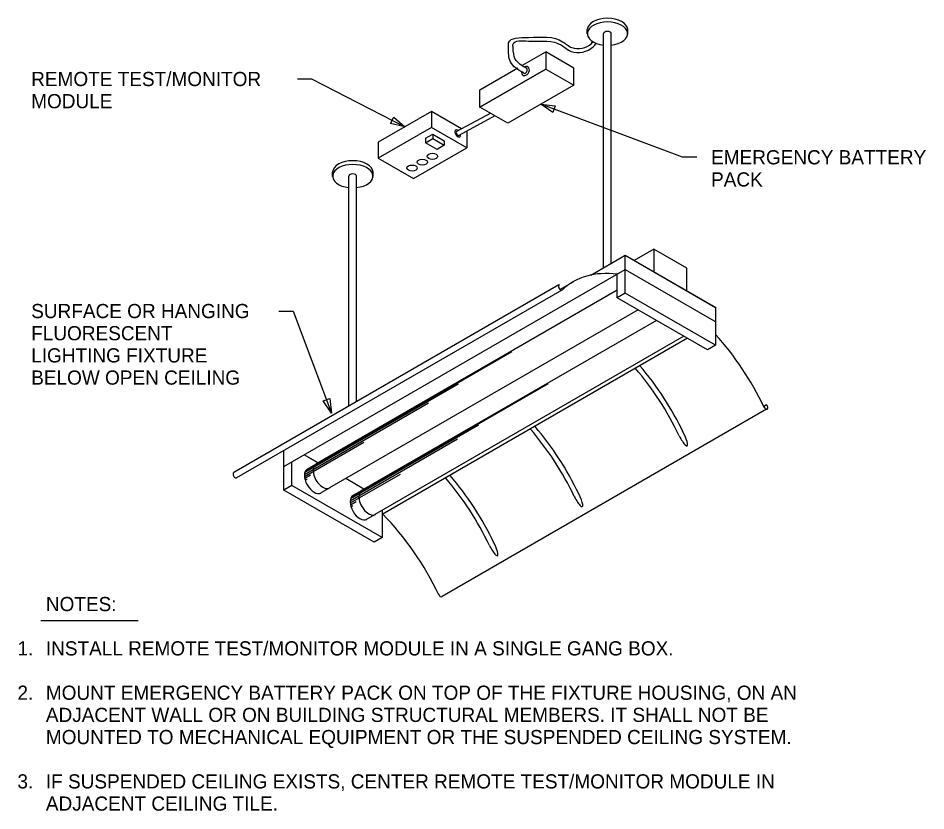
# Model space of a CAD drawing. Extents: x -12092.5 to -12048.3, y -12283.2 to -12205.8.
# Drawn here: x -12091.75 to -12049.13, y -12243.02 to -12205.78 of the extents above; entities that cross this region are included whole.
import ezdxf

# ---------------------------------------------------------------- set-up
doc = ezdxf.new("R2010")
doc.units = 0
for name, color, linetype in [('G-ANNO-TEXT', 7, 'Continuous'), ('G-DETL-LINE', 7, 'Continuous'), ('G-DETL-OTLN', 7, 'Continuous'), ('G-DETL-PATT', 7, 'Continuous')]:
    doc.layers.add(name, color=color, linetype=linetype)

msp = doc.modelspace()

# ---------------------------------------------------------------- linework, layer by layer
at = {"layer": 'G-ANNO-TEXT'}
for p, q in [((-12078.644, -12208.636), (-12077.977, -12208.636)), ((-12077.977, -12208.636), (-12073.601, -12210.884)), ((-12060.552, -12212.314), (-12067.216, -12209.819)), ((-12059.885, -12212.314), (-12060.552, -12212.314)), ((-12079.515, -12219.539), (-12078.848, -12219.539)), ((-12078.848, -12219.539), (-12077.045, -12224.331)), ((-12090.687, -12234.076), (-12086.127, -12234.076))]:
    msp.add_line(p, q, dxfattribs=at)
for points in [[(-12066.65, -12210.209), (-12067.216, -12209.819), (-12066.533, -12209.897)], [(-12074.118, -12210.431), (-12073.601, -12210.884), (-12074.271, -12210.728)], [(-12077.124, -12223.648), (-12077.045, -12224.331), (-12077.436, -12223.765)]]:
    msp.add_lwpolyline(points, close=True, dxfattribs=at)
at = {"layer": 'G-DETL-LINE'}
for p, q in [((-12063.629, -12218.559), (-12077.781, -12226.73)), ((-12062.643, -12219.484), (-12077.131, -12227.849)), ((-12061.786, -12219.978), (-12075.629, -12227.971)), ((-12060.492, -12220.726), (-12075.004, -12229.104))]:
    msp.add_line(p, q, dxfattribs=at)
for centre, major_axis, ratio, start_param, end_param in [((-12065.474, -12226.817), (-4.221, 7.311), 0.57735, 4.575874, 5.027866), ((-12065.263, -12226.695), (-4.221, 7.311), 0.57735, 4.575874, 5.027851), ((-12070.186, -12229.552), (-4.221, 7.311), 0.57735, 4.575874, 5.027851), ((-12070.398, -12229.674), (-4.221, 7.311), 0.57735, 4.575874, 5.027866), ((-12060.612, -12225.337), (0.271, -0.537), 0.202786, 4.723764, 7.865371), ((-12074.38, -12231.977), (-4.221, 7.311), 0.57735, 4.575874, 5.027866), ((-12074.168, -12231.855), (-4.221, 7.311), 0.57735, 4.575874, 5.027851), ((-12065.536, -12228.194), (0.271, -0.537), 0.202786, 4.723764, 7.865371), ((-12069.518, -12230.497), (0.271, -0.537), 0.202786, 4.723764, 7.865371)]:
    msp.add_ellipse(centre, major_axis=major_axis, ratio=ratio, start_param=start_param, end_param=end_param, dxfattribs=at)
at = {"layer": 'G-DETL-OTLN'}
for p, q in [((-12065.034, -12206.522), (-12065.034, -12206.311)), ((-12064.262, -12217.503), (-12064.262, -12206.505)), ((-12063.902, -12217.295), (-12063.902, -12206.505)), ((-12063.132, -12206.524), (-12063.132, -12206.313)), ((-12068.067, -12207.988), (-12066.983, -12207.361)), ((-12065.668, -12208.121), (-12066.983, -12207.361)), ((-12066.983, -12207.361), (-12066.983, -12208.167)), ((-12066.983, -12207.361), (-12066.983, -12208.168)), ((-12070.077, -12209.148), (-12068.294, -12208.119)), ((-12070.077, -12209.955), (-12066.981, -12208.167)), ((-12066.983, -12208.168), (-12070.077, -12209.955)), ((-12066.983, -12208.167), (-12065.668, -12208.926)), ((-12066.981, -12208.167), (-12065.668, -12208.926)), ((-12065.668, -12208.926), (-12065.668, -12208.121)), ((-12070.077, -12209.955), (-12070.077, -12209.148)), ((-12065.668, -12208.926), (-12068.763, -12210.713)), ((-12068.763, -12210.713), (-12070.077, -12209.955)), ((-12072.353, -12210.163), (-12074.85, -12211.605)), ((-12072.353, -12210.163), (-12072.353, -12210.916)), ((-12070.931, -12210.983), (-12072.353, -12210.163)), ((-12069.567, -12210.249), (-12071.166, -12211.11)), ((-12069.364, -12210.371), (-12071.064, -12211.286)), ((-12072.353, -12210.916), (-12074.85, -12212.358)), ((-12070.691, -12211.875), (-12072.353, -12210.916)), ((-12072.626, -12211.42), (-12072.288, -12211.225)), ((-12072.288, -12211.225), (-12072.288, -12211.438)), ((-12072.288, -12211.225), (-12071.747, -12211.537)), ((-12070.691, -12211.122), (-12070.724, -12211.103)), ((-12070.691, -12211.122), (-12070.691, -12211.875)), ((-12074.85, -12211.605), (-12074.85, -12212.358)), ((-12072.626, -12211.42), (-12072.626, -12211.633)), ((-12072.626, -12211.633), (-12072.288, -12211.438)), ((-12072.085, -12211.945), (-12072.626, -12211.633)), ((-12072.288, -12211.438), (-12071.747, -12211.75)), ((-12071.747, -12211.75), (-12072.085, -12211.945)), ((-12071.747, -12211.537), (-12071.747, -12211.75)), ((-12073.189, -12213.318), (-12070.691, -12211.875)), ((-12074.85, -12212.358), (-12073.189, -12213.318)), ((-12076.993, -12213.218), (-12076.993, -12213.008)), ((-12075.091, -12213.22), (-12075.091, -12213.01)), ((-12076.221, -12224), (-12076.221, -12213.202)), ((-12075.861, -12223.792), (-12075.861, -12213.202)), ((-12061.905, -12216.63), (-12062.831, -12217.165)), ((-12061.905, -12216.63), (-12061.905, -12217.699)), ((-12060.357, -12217.523), (-12061.905, -12216.63)), ((-12064.864, -12217.85), (-12063.254, -12216.92)), ((-12063.254, -12217.595), (-12063.254, -12216.92)), ((-12063.254, -12216.92), (-12059.008, -12219.372)), ((-12063.254, -12218.698), (-12063.254, -12216.92)), ((-12063.254, -12216.92), (-12058.997, -12219.378)), ((-12079.276, -12226.845), (-12063.254, -12217.595)), ((-12063.254, -12217.595), (-12058.997, -12220.053)), ((-12061.905, -12217.699), (-12060.357, -12218.593)), ((-12060.357, -12218.593), (-12060.357, -12217.523)), ((-12066.312, -12218.525), (-12065.664, -12218.149)), ((-12063.629, -12218.914), (-12063.629, -12217.812)), ((-12066.359, -12218.307), (-12081.631, -12227.124)), ((-12066.225, -12218.555), (-12081.496, -12227.372)), ((-12063.254, -12218.698), (-12063.629, -12218.914)), ((-12059.384, -12221.366), (-12063.629, -12218.914)), ((-12059.008, -12221.15), (-12063.254, -12218.698)), ((-12059.008, -12219.372), (-12059.008, -12221.15)), ((-12058.997, -12219.378), (-12059.008, -12219.385)), ((-12058.997, -12220.053), (-12059.008, -12220.059)), ((-12060.327, -12220.821), (-12074.655, -12229.093)), ((-12059.008, -12221.15), (-12059.384, -12221.366)), ((-12056.611, -12224.157), (-12071.847, -12232.954)), ((-12056.611, -12223.941), (-12056.746, -12224.02)), ((-12079.276, -12227.949), (-12079.276, -12226.099)), ((-12078.901, -12227.733), (-12078.901, -12226.628)), ((-12077.67, -12226.665), (-12078.317, -12226.292)), ((-12078.178, -12226.372), (-12077.67, -12226.665)), ((-12078.189, -12226.965), (-12077.781, -12226.73)), ((-12075.519, -12227.907), (-12076.375, -12227.413)), ((-12078.901, -12227.733), (-12079.276, -12227.949)), ((-12075.03, -12230.4), (-12079.276, -12227.949)), ((-12074.655, -12230.184), (-12078.901, -12227.733)), ((-12077.538, -12228.084), (-12077.131, -12227.849)), ((-12076.037, -12228.206), (-12075.629, -12227.971)), ((-12075.411, -12229.339), (-12075.004, -12229.104)), ((-12074.655, -12228.903), (-12074.655, -12230.184)), ((-12074.655, -12230.184), (-12075.03, -12230.4))]:
    msp.add_line(p, q, dxfattribs=at)
for centre, major_axis, ratio, start_param, end_param in [((-12064.082, -12206.326), (0.949, 0), 0.57735, 0.023055, 3.115122), ((-12064.082, -12206.505), (0.949, 0), 0.57735, 4.903098, 10.804856), ((-12064.082, -12206.505), (0.18, 0), 0.57735, 0.000014, 3.141593), ((-12067.937, -12208.259), (0.113, 0.196), 0.763775, 2.006341, 7.128248), ((-12067.937, -12208.259), (0.063, 0.11), 0.57735, 2.886861, 6.283199), ((-12071.112, -12211.196), (-0.094, 0.163), 0.57735, 5.265466, 10.405225), ((-12071.112, -12211.196), (-0.0509, 0.0882), 0.57735, 0.070062, 3.085509), ((-12076.041, -12213.022), (0.949, 0), 0.57735, 0.023055, 3.115122), ((-12076.041, -12213.202), (0.949, 0), 0.57735, 4.903098, 10.804856), ((-12076.041, -12213.202), (0.18, 0), 0.57735, 0.000014, 3.141593), ((-12061.482, -12225.483), (-4.221, 7.311), 0.57735, 5.86579, 6.413493), ((-12066.286, -12218.428), (-0.071, 0.122), 0.57735, 6.078974, 9.424861), ((-12061.482, -12225.483), (-4.221, 7.311), 0.57735, 4.575874, 5.070602), ((-12056.654, -12224.023), (-0.071, 0.122), 0.57735, 1.217457, 5.065729), ((-12081.567, -12227.25), (-0.071, 0.122), 0.57735, 6.078974, 9.424861), ((-12077.855, -12227.526), (-0.324, 0.561), 0.57735, 0.000024, 3.126749), ((-12077.446, -12227.292), (-0.324, 0.561), 0.57735, 6.283165, 9.424762), ((-12075.296, -12228.534), (-0.324, 0.561), 0.57735, 6.283165, 9.424762), ((-12075.704, -12228.768), (-0.324, 0.561), 0.57735, 0.000024, 3.126749), ((-12076.753, -12234.3), (-4.221, 7.311), 0.57735, 4.575874, 5.134547), ((-12071.932, -12232.835), (-0.071, 0.122), 0.57735, 1.217457, 3.291614)]:
    msp.add_ellipse(centre, major_axis=major_axis, ratio=ratio, start_param=start_param, end_param=end_param, dxfattribs=at)
for centre in [(-12072.304, -12212.271), (-12072.775, -12212.543), (-12073.259, -12212.822)]:
    msp.add_ellipse(centre, major_axis=(0.246, 0), ratio=0.57735, dxfattribs=at)
for points in [[(-12068.733, -12207.187), (-12068.724, -12206.941), (-12067.798, -12206.684), (-12066.189, -12206.883), (-12065.757, -12207.161), (-12064.836, -12206.967), (-12064.762, -12206.888)], [(-12068.514, -12207.176), (-12068.514, -12206.996), (-12067.792, -12206.853), (-12066.247, -12207.043), (-12065.789, -12207.339), (-12064.75, -12207.119), (-12064.607, -12206.967)], [(-12068.007, -12208.361), (-12068.639, -12207.828), (-12068.731, -12207.163)], [(-12067.874, -12208.148), (-12068.41, -12207.704), (-12068.514, -12207.176)]]:
    msp.add_spline(points, degree=3, dxfattribs=at)
at = {"layer": 'G-DETL-PATT'}
for p, q in [((-12068.571, -12221.46), (-12078.266, -12227.058)), ((-12071.099, -12222.968), (-12078.294, -12227.122)), ((-12066.868, -12222.96), (-12076.116, -12228.3)), ((-12072.492, -12223.869), (-12078.312, -12227.229)), ((-12070.145, -12224.9), (-12076.143, -12228.364)), ((-12075.53, -12225.719), (-12078.31, -12227.324)), ((-12071.124, -12225.562), (-12076.162, -12228.47)), ((-12078.027, -12227.257), (-12078.296, -12227.412)), ((-12078.177, -12227.44), (-12078.274, -12227.496)), ((-12073.823, -12227.216), (-12076.159, -12228.565)), ((-12075.889, -12228.506), (-12076.146, -12228.654)), ((-12076.038, -12228.687), (-12076.124, -12228.737))]:
    msp.add_line(p, q, dxfattribs=at)

# ---------------------------------------------------------------- texts
at = {"layer": 'G-ANNO-TEXT'}
for s, height, p in [('REMOTE TEST/MONITOR', 0.66667, (-12091.142, -12208.97)), ('MODULE', 0.6667, (-12091.142, -12210.011)), ('EMERGENCY BATTERY', 0.66667, (-12059.219, -12212.647)), ('PACK', 0.6667, (-12059.219, -12213.689)), ('SURFACE OR HANGING', 0.66667, (-12091.142, -12219.873)), ('FLUORESCENT', 0.66667, (-12091.142, -12220.914)), ('LIGHTING FIXTURE', 0.66667, (-12091.142, -12221.956)), ('BELOW OPEN CEILING', 0.66667, (-12091.142, -12222.998)), ('NOTES:', 0.6667, (-12090.453, -12233.639)), ('1.', 0.6667, (-12091.788, -12235.722)), ('INSTALL REMOTE TEST/MONITOR MODULE IN A SINGLE GANG BOX.', 0.66667, (-12090.453, -12235.722)), ('2.', 0.6667, (-12091.788, -12237.806)), ('MOUNT EMERGENCY BATTERY PACK ON TOP OF THE FIXTURE HOUSING, ON AN', 0.66667, (-12090.453, -12237.806)), ('ADJACENT WALL OR ON BUILDING STRUCTURAL MEMBERS. IT SHALL NOT BE', 0.66667, (-12090.453, -12238.847)), ('MOUNTED TO MECHANICAL EQUIPMENT OR THE SUSPENDED CEILING SYSTEM.', 0.66667, (-12090.453, -12239.889)), ('3.', 0.6667, (-12091.788, -12241.972)), ('IF SUSPENDED CEILING EXISTS, CENTER REMOTE TEST/MONITOR MODULE IN', 0.66667, (-12090.453, -12241.972)), ('ADJACENT CEILING TILE.', 0.66667, (-12090.453, -12243.014))]:
    msp.add_text(s, height=height, dxfattribs=at).set_placement(p)

doc.saveas('drawing.dxf')
